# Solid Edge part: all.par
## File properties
Author: f_grande
Template: Normal.par
Last saved by: f_grande
Revision: 1
Application: Solid Edge
Densità: 2712,000 kg/m^3
Precisione: 0,990
Tipo di contenuto documento: 0
Material: Alluminio, 1060
Stile della faccia: Alluminio
Stile di riempimento: ANSI38(Alluminio)
Stile virtuale: Alluminio lucidato
Coef. of Thermal Exp: 0.0
Thermal Conductivity: 221.0
Specific Heat: 920.0
Modulus of Elasticity: 68947570000.0
Poisson's Ratio: 0.33
Yield Stress: 27579028.0
Ultimate Stress: 68947570.0
Elongation: 0.0
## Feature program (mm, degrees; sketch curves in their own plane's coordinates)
sketch for "unnamed Protrusion 1" #1 plane through (0, 0, 0) normal (0, 0, 1) x-axis (1, 0, 0)
  circle centre (23.25, 23.25) radius 3
sketch for "unnamed Protrusion 1" #2 plane through (0, 0, 0) normal (0, 0, 1) x-axis (1, 0, 0)
  line (30.15, 11.854) -> (30.15, 0)
  line (30.15, 0) -> (25, 0)
  line (0, 26.95) -> (0, 25)
  line (5.6846, 26.95) -> (0, 26.95)
  arc centre (5.6846, 27.35) radius 0.4 from (5.6846, 26.95) to (6.0378, 27.5377) ccw
  line (5.5, 28.55) -> (6.0378, 27.5377)
  line (5.5, 30.15) -> (5.5, 28.55)
  line (5.5, 30.15) -> (24.15, 30.15)
  arc centre (24.15, 24.15) radius 6 from (24.15, 30.15) to (30.15, 24.15) cw
  line (30.15, 24.15) -> (30.15, 18.3116)
  arc centre (29.65, 18.3116) radius 0.5 from (30.15, 18.3116) to (29.65, 17.8116) cw
  line (29.65, 17.8116) -> (28.7, 17.8116)
  line (28.7, 17.8116) -> (28.7, 18.2366)
  arc centre (28.45, 18.2366) radius 0.25 from (28.45, 18.4866) to (28.7, 18.2366) cw
  line (28.45, 18.4866) -> (25.85, 18.4866)
  arc centre (25.85, 17.6866) radius 0.8 from (25.85, 18.4866) to (25.05, 17.6866) ccw
  line (25.05, 17.6866) -> (25.05, 12.4866)
  arc centre (25.85, 12.4866) radius 0.8 from (25.85, 11.6866) to (25.05, 12.4866) cw
  line (25.85, 11.6866) -> (28.45, 11.6866)
  arc centre (28.45, 11.9366) radius 0.25 from (28.45, 11.6866) to (28.7, 11.9366) ccw
  line (28.7, 11.9366) -> (28.7, 12.3616)
  line (28.7, 12.3616) -> (29.654, 12.354)
  arc centre (29.65, 11.854) radius 0.5 from (30.15, 11.854) to (29.654, 12.354) ccw
extrude "unnamed Protrusion 1" add finite 1000 along +normal
body pattern "unnamed BodyPattern 1"
pattern "unnamed Pattern 1"
body pattern "unnamed BodyPattern 2"
pattern "unnamed Pattern 2"
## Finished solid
Body 1: solid body, 87 faces, 250 edges, 160 vertices.
  Faces by surface: plane 50, cylinder 37
  Edges by curve: line 176, circle 74
Bounding box of the edges (mm): 60.300 x 60.300 x 1000.000, from (-30.15, -30.15, 0) to (30.15, 30.15, 1000).
Cylindrical faces by radius (mm): R0.25 x8, R0.4 x4, R0.5 x8, R0.8 x8, R3 x4, R6 x4, R25 x1
Planar faces by outward normal: +x 11, +y 9, +z 1, -x 11, -y 9, -z 1, oblique 8
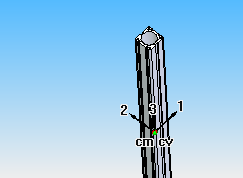
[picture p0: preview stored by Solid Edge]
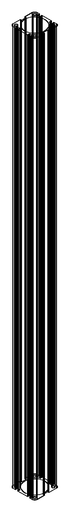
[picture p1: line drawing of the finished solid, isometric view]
